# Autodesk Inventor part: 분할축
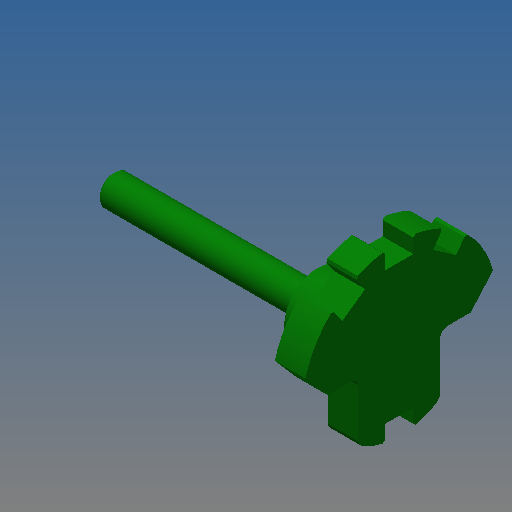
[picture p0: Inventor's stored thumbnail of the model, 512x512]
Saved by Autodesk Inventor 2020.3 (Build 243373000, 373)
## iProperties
Created: 2016-11
Part Number: 분할축
Material: 강철, 연강
Document SubType Name: Modeling
Designer: mduedu
Density: 1 g/cm^3
Appearance: 진녹색
Author: mduedu
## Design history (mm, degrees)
sketch "스케치1"
  geometry: C1 r 38 at (0, 0); 1 further point
  constraints: 1 centre point, 1 coincident
  dimensions: "d0" = 76 diameter of C1
extrude "돌출1" new body sketch "스케치1" distance "d1" = 12; taper "d2" = 0 deg
sketch "스케치2"
  geometry: L1 (0, 38)-(0, -38); L2 (5.5, 37.6)-(5.5, 31); L3 (5.5, 31)-(-5.5, 31); L4 (-5.5, 31)-(-5.5, 37.6); A1 r 38 centre (0, 0) between (0, 38) and (0, -38) reference; A2 r 38 centre (0, 0) between (5.5, 37.6) and (-5.5, 37.6); 2 further points
  constraints: 8 end point, 6 point on circle, 2 coincident, 2 vertical, 1 centre point, 1 horizontal, 1 midpoint, 1 parallel, 1 symmetric about line
  dimensions: "d3" = 11 distance of L2.end L3.end; "d5" = 31 distance from line of L3 point (0, 0)
extrude "돌출2" cut sketch "스케치2" extent not by distance; stored distance "d7" = 12; taper "d8" = 0 deg
sketch "스케치3"
  geometry: L1 (-16, 0)-(-38, 0); L2 (16, 0)-(38, 0); L3 (0, -28)-(0, 28); L4 (-16, -22.978)-(-16, 0); L5 (16, -22.978)-(16, 0); A1 r 38 centre (0, 0) between (-5.5, 37.6) and (-17.061, 33.955) reference; A2 r 38 centre (0, 0) between (-38, 0) and (38, 0); A3 r 28 centre (0, 0) between (-16, -22.978) and (16, -22.978); 4 further points
  constraints: 10 end point, 7 point on circle, 3 coincident, 2 centre point, 2 horizontal alignment, 2 midpoint, 2 parallel, 1 collinear, 1 horizontal, 1 perpendicular, 1 other
  dimensions: "d13" = 32 distance between parallel lines of L5 L4; "d14" = 28 radius of A3
extrude "돌출3" cut sketch "스케치3" extent not by distance; stored distance "d15" = 12; taper "d16" = 0 deg
sketch "스케치4"
  geometry: L1 (0, 0)-(0, -28); L2 (5.5, -27.455)-(5.5, -21); L3 (5.5, -21)-(-5.5, -21); L4 (-5.5, -21)-(-5.5, -27.455); A1 r 28 centre (0, 0) between (-16, -22.978) and (16, -22.978) reference; A2 r 28 centre (0, 0) between (16, -22.978) and (0, -28); A3 r 28 centre (0, 0) between (-5.5, -27.455) and (5.5, -27.455); 1 further point
  constraints: 8 end point, 7 point on circle, 2 centre point, 2 coincident, 1 horizontal, 1 parallel, 1 other
  dimensions: "d17" = 11 distance between parallel lines of L2 L4; "d19" = 21 distance from line of L3 point (0, 0)
extrude "돌출4" cut sketch "스케치4" extent not by distance; stored distance "d20" = 12; taper "d21" = 0 deg
sketch "스케치5"
  geometry: C1 r 13 at (0, 0); 1 further point
  constraints: 1 centre point, 1 coincident
  dimensions: "d22" = 26 diameter of C1
extrude "돌출5" join sketch "스케치5" distance "d23" = 20; taper "d24" = 0 deg
sketch "스케치6"
  geometry: C1 r 6 at (0, 0); 1 further point
  constraints: 1 centre point, 1 coincident
  dimensions: "d25" = 12 diameter of C1
extrude "돌출6" join sketch "스케치6" distance "d26" = 80; taper "d27" = 0 deg
fillet "모깎기1" dims "d28" = 3
chamfer "모따기1" distance "d29" = 1; stored, may be unused: second distance "d30" = 2, angle "d31" = 45 deg
sketch "스케치7"
  geometry: L1 (-20, 13)-(-20, -13) reference; L2 (-20, 6)-(-99, 6) reference; L3 (0, 0)-(-20, 0); C1 r 1 at (-21, 6)
  constraints: 2 end point, 1 centre point, 1 midpoint, 1 tangent
  dimensions: "d32" = 2 diameter of C1; "d33" = 10 dimension on C1 L3
revolve "회전1" sketch "스케치7" stored, may be unused: angle "d34" = 90 deg
chamfer "모따기2" distance "d35" = 1; stored, may be unused: second distance "d36" = 2, angle "d37" = 45 deg
chamfer "모따기3" distance "d38" = 10; stored, may be unused: second distance "d39" = 2, angle "d40" = 45 deg
chamfer "모따기4" distance "d41" = 1; stored, may be unused: second distance "d42" = 2, angle "d43" = 45 deg
fillet "모깎기2" dims "d44" = 3
node "솔리드1"
pattern_circular "원형 패턴1" dims angle "d10" = 35 deg
other parameters: "d12" = 56
